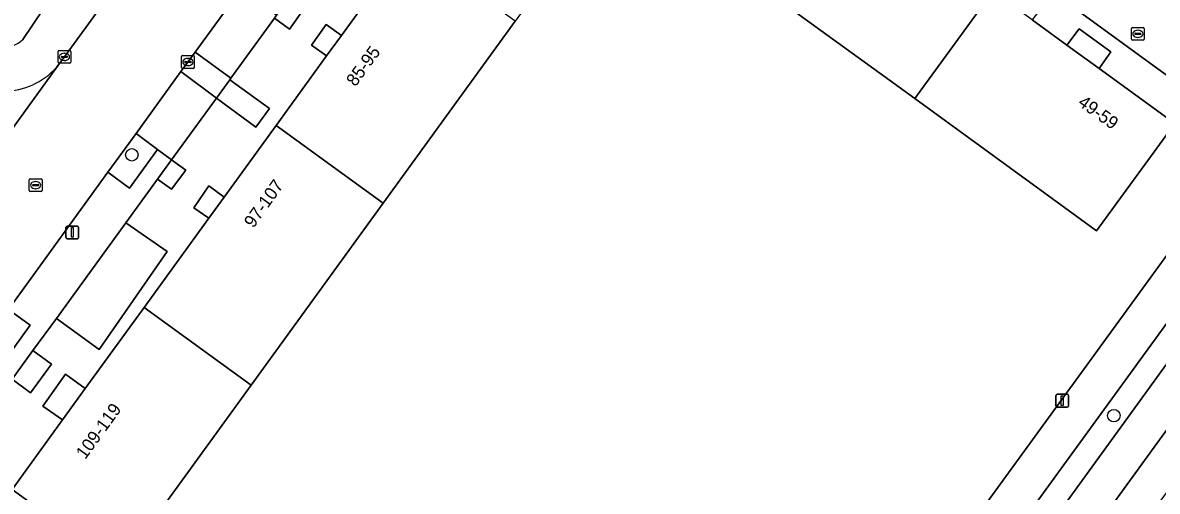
# Model space of a CAD drawing. Extents: x 159674 to 160531, y 382172 to 382904.
# Drawn here: x 160250.3 to 160339.1, y 382520.6 to 382557.3 of the extents above; entities that cross this region are included whole.
import ezdxf

# ---------------------------------------------------------------- set-up
doc = ezdxf.new("R2010")
doc.units = 0
for name, color, linetype in [('IMGEO_Berm_groen', 7, 'Continuous'), ('IMGEO_Boom', 7, 'Continuous'), ('IMGEO_Brandkraan', 7, 'Continuous'), ('IMGEO_Erf', 7, 'Continuous'), ('IMGEO_Fietspad_gesloten', 7, 'Continuous'), ('IMGEO_Groenvoorziening', 7, 'Continuous'), ('IMGEO_Haag', 7, 'Continuous'), ('IMGEO_Kolk', 7, 'Continuous'), ('IMGEO_Lichtmast', 7, 'Continuous'), ('IMGEO_Pand', 7, 'Continuous'), ('IMGEO_Pand_nummerreeks', 7, 'Continuous'), ('IMGEO_Rijbaan_lokaal_gesloten', 7, 'Continuous'), ('IMGEO_Rijbaan_lokaal_open', 7, 'Continuous'), ('IMGEO_Rioolput', 7, 'Continuous'), ('IMGEO_Voetpad_open', 7, 'Continuous')]:
    doc.layers.add(name, color=color, linetype=linetype)

msp = doc.modelspace()

# ---------------------------------------------------------------- linework, layer by layer
at = {"layer": 'IMGEO_Berm_groen'}
for points in [[(160349.002, 382543.246), (160398.827, 382611.342), (160398.73, 382611.41), (160397.047, 382612.59), (160360.539, 382562.246), (160346.84, 382543.397), (160315.294, 382500), (160291.256, 382466.928), (160255.648, 382417.937), (160257.187, 382416.772), (160266.645, 382429.855), (160311.53, 382491.554)], [(160343.873, 382526.012), (160345.353, 382528.03), (160352.635, 382538.399), (160362.897, 382552.659), (160374.83, 382569.169), (160378.396, 382574.452), (160390.705, 382592.122), (160401.931, 382608.929), (160401.131, 382609.485), (160351.662, 382541.731), (160259.615, 382414.865), (160260.653, 382414.245), (160291.094, 382453.563), (160297.701, 382462.662), (160324.815, 382500)]]:
    msp.add_lwpolyline(points, close=True, dxfattribs=at)
at = {"layer": 'IMGEO_Boom'}
for centre in [(160258.813, 382546.917), (160335.675, 382526.506)]:
    msp.add_circle(centre, 0.489, dxfattribs=at)
at = {"layer": 'IMGEO_Brandkraan'}
for p, q in [((160337.057, 382555.962), (160337.057, 382556.814)), ((160337.132, 382556.888), (160337.984, 382556.888)), ((160337.545, 382556.668), (160337.57, 382556.668)), ((160338.058, 382556.814), (160338.058, 382555.962)), ((160337.984, 382555.888), (160337.132, 382555.888)), ((160337.316, 382556.382), (160337.316, 382556.394)), ((160337.754, 382556.345), (160337.356, 382556.345)), ((160337.359, 382556.431), (160337.757, 382556.431)), ((160337.568, 382556.108), (160337.543, 382556.108)), ((160337.8, 382556.394), (160337.8, 382556.382))]:
    msp.add_line(p, q, dxfattribs=at)
for points in [[(160337.057, 382555.962), (160337.057, 382556.814)], [(160337.132, 382556.888), (160337.984, 382556.888)], [(160338.058, 382556.814), (160338.058, 382555.962)], [(160337.984, 382555.888), (160337.132, 382555.888)]]:
    msp.add_lwpolyline(points, dxfattribs=at)
for centre, radius, start, end in [((160337.134, 382556.812), 0.0765, 91.55205, 178.44795), ((160337.134, 382556.812), 0.0765, 91.55205, 178.44795), ((160337.982, 382556.812), 0.0765, 1.55205, 88.44795), ((160337.982, 382556.812), 0.0765, 1.55205, 88.44795), ((160337.134, 382555.964), 0.0765, 181.55205, 268.44795), ((160337.134, 382555.964), 0.0765, 181.55205, 268.44795), ((160337.356, 382556.391), 0.0403, 85.87752, 175.75265), ((160337.353, 382556.381), 0.0366, 178.93798, 274.71019), ((160337.757, 382556.388), 0.043, 264.86636, 352.45326), ((160337.761, 382556.393), 0.0386, 1.73085, 96.63898), ((160337.982, 382555.964), 0.0765, 271.55205, 358.44795), ((160337.982, 382555.964), 0.0765, 271.55205, 358.44795)]:
    msp.add_arc(centre, radius, start, end, dxfattribs=at)
for centre, major_axis, ratio, start_param, end_param in [((160337.544, 382556.388), (-0.387, 0.002), 0.722429, 4.712389, 7.853982), ((160337.569, 382556.388), (-0.39, 0.002), 0.717154, 1.570796, 4.712389)]:
    msp.add_ellipse(centre, major_axis=major_axis, ratio=ratio, start_param=start_param, end_param=end_param, dxfattribs=at)
at = {"layer": 'IMGEO_Erf'}
msp.add_lwpolyline([(160250.273, 382555.941), (160251.85, 382558.275), (160246.728, 382562), (160241.969, 382565.462), (160237.179, 382568.945)], dxfattribs=at)
msp.add_arc((160248.4, 382557.973), 2.764, 274.80019, 312.67073, dxfattribs=at)
at = {"layer": 'IMGEO_Fietspad_gesloten'}
msp.add_lwpolyline([(160351.662, 382541.731), (160401.131, 382609.485), (160403.23, 382612.508), (160404.299, 382614.103), (160401.904, 382615.599), (160398.827, 382611.342), (160349.002, 382543.246), (160311.53, 382491.554), (160266.645, 382429.855), (160257.187, 382416.772), (160254.673, 382413.295), (160254.433, 382412.964), (160257.305, 382411.797), (160259.615, 382414.865)], close=True, dxfattribs=at)
at = {"layer": 'IMGEO_Groenvoorziening'}
for points in [[(160340.442, 382549.369), (160334.331, 382540.968), (160330.288, 382543.909), (160320.097, 382551.321), (160305.863, 382561.673), (160309.033, 382566.031), (160311.974, 382570.074), (160312.894, 382569.405), (160313.791, 382570.579), (160311.658, 382572.109), (160310.584, 382571.385), (160308.218, 382568.127), (160290.343, 382581.143), (160288.198, 382582.705), (160286.206, 382579.962), (160290.265, 382577.019), (160290.699, 382577.618), (160299.084, 382571.539), (160288.827, 382557.394), (160278.496, 382543.145), (160268.164, 382528.897), (160257.833, 382514.648), (160249.448, 382520.727)], [(160293.252, 382483.855), (160291.445, 382481.395), (160295.603, 382478.257), (160311.42, 382500), (160344.923, 382546.056)]]:
    msp.add_lwpolyline(points, dxfattribs=at)
for points in [[(160272.323, 382560.849), (160270.141, 382557.844), (160269.982, 382557.625), (160271.161, 382556.768), (160273.472, 382560.037)], [(160275.215, 382556.263), (160274.018, 382557.131), (160272.871, 382555.506), (160274.059, 382554.669)], [(160332.008, 382555.503), (160334.533, 382553.667), (160335.437, 382554.991), (160332.951, 382556.772)], [(160266.478, 382552.801), (160265.433, 382551.363), (160268.508, 382549.076), (160269.594, 382550.536)], [(160260.836, 382547.345), (160259.145, 382548.59), (160256.944, 382545.554), (160258.645, 382544.321)], [(160261.93, 382546.54), (160260.827, 382545.022), (160261.924, 382544.225), (160263.031, 382545.73)], [(160266.042, 382543.613), (160264.845, 382544.481), (160263.67, 382542.781), (160264.849, 382541.967)], [(160258.34, 382541.598), (160252.908, 382534.119), (160256.263, 382531.683), (160261.573, 382539.364)], [(160249.155, 382534.809), (160247.218, 382532.137), (160248.919, 382530.904), (160250.856, 382533.576)], [(160251.073, 382531.592), (160249.443, 382529.348), (160250.883, 382528.287), (160252.536, 382530.53)], [(160255.17, 382528.62), (160253.623, 382529.742), (160251.861, 382527.246), (160253.392, 382526.166)]]:
    msp.add_lwpolyline(points, close=True, dxfattribs=at)
at = {"layer": 'IMGEO_Haag'}
msp.add_lwpolyline([(160332.008, 382555.503), (160334.533, 382553.667), (160335.437, 382554.991), (160332.951, 382556.772)], close=True, dxfattribs=at)
at = {"layer": 'IMGEO_Kolk'}
for p, q in [((160253.038, 382554.16), (160253.038, 382555.012)), ((160253.113, 382555.086), (160253.965, 382555.086)), ((160253.526, 382554.866), (160253.551, 382554.866)), ((160254.039, 382555.012), (160254.039, 382554.16)), ((160253.965, 382554.086), (160253.113, 382554.086)), ((160253.297, 382554.58), (160253.297, 382554.592)), ((160253.735, 382554.543), (160253.337, 382554.543)), ((160253.34, 382554.629), (160253.738, 382554.629)), ((160253.549, 382554.306), (160253.524, 382554.306)), ((160253.781, 382554.592), (160253.781, 382554.58)), ((160262.704, 382553.762), (160262.704, 382554.614)), ((160262.779, 382554.688), (160263.631, 382554.688)), ((160262.963, 382554.182), (160262.963, 382554.194)), ((160263.401, 382554.145), (160263.003, 382554.145)), ((160263.006, 382554.231), (160263.404, 382554.231)), ((160263.192, 382554.468), (160263.217, 382554.468)), ((160263.447, 382554.194), (160263.447, 382554.182)), ((160263.705, 382554.614), (160263.705, 382553.762)), ((160263.631, 382553.688), (160262.779, 382553.688)), ((160263.215, 382553.908), (160263.19, 382553.908))]:
    msp.add_line(p, q, dxfattribs=at)
for points in [[(160253.038, 382554.16), (160253.038, 382555.012)], [(160253.113, 382555.086), (160253.965, 382555.086)], [(160254.039, 382555.012), (160254.039, 382554.16)], [(160253.965, 382554.086), (160253.113, 382554.086)], [(160262.704, 382553.762), (160262.704, 382554.614)], [(160262.779, 382554.688), (160263.631, 382554.688)], [(160263.705, 382554.614), (160263.705, 382553.762)], [(160263.631, 382553.688), (160262.779, 382553.688)]]:
    msp.add_lwpolyline(points, dxfattribs=at)
for centre, radius, start, end in [((160253.115, 382555.01), 0.0765, 91.55205, 178.44795), ((160253.115, 382555.01), 0.0765, 91.55205, 178.44795), ((160253.963, 382555.01), 0.0765, 1.55205, 88.44795), ((160253.963, 382555.01), 0.0765, 1.55205, 88.44795), ((160253.115, 382554.162), 0.0765, 181.55205, 268.44795), ((160253.115, 382554.162), 0.0765, 181.55205, 268.44795), ((160253.337, 382554.589), 0.0403, 85.87752, 175.75265), ((160253.334, 382554.579), 0.0366, 178.93798, 274.71019), ((160253.738, 382554.586), 0.043, 264.86636, 352.45326), ((160253.742, 382554.591), 0.0386, 1.73085, 96.63898), ((160253.963, 382554.162), 0.0765, 271.55205, 358.44795), ((160253.963, 382554.162), 0.0765, 271.55205, 358.44795), ((160262.781, 382554.612), 0.0765, 91.55205, 178.44795), ((160262.781, 382554.612), 0.0765, 91.55205, 178.44795), ((160263.003, 382554.191), 0.0403, 85.87752, 175.75265), ((160263, 382554.181), 0.0366, 178.93798, 274.71019), ((160263.404, 382554.188), 0.043, 264.86636, 352.45326), ((160263.408, 382554.193), 0.0386, 1.73085, 96.63898), ((160263.629, 382554.612), 0.0765, 1.55205, 88.44795), ((160263.629, 382554.612), 0.0765, 1.55205, 88.44795), ((160262.781, 382553.764), 0.0765, 181.55205, 268.44795), ((160262.781, 382553.764), 0.0765, 181.55205, 268.44795), ((160263.629, 382553.764), 0.0765, 271.55205, 358.44795), ((160263.629, 382553.764), 0.0765, 271.55205, 358.44795)]:
    msp.add_arc(centre, radius, start, end, dxfattribs=at)
for centre, major_axis, ratio, start_param, end_param in [((160253.525, 382554.586), (-0.387, 0.002), 0.722429, 4.712389, 7.853982), ((160253.55, 382554.586), (-0.39, 0.002), 0.717154, 1.570796, 4.712389), ((160263.191, 382554.188), (-0.387, 0.002), 0.722429, 4.712389, 7.853982), ((160263.216, 382554.188), (-0.39, 0.002), 0.717154, 1.570796, 4.712389)]:
    msp.add_ellipse(centre, major_axis=major_axis, ratio=ratio, start_param=start_param, end_param=end_param, dxfattribs=at)
at = {"layer": 'IMGEO_Lichtmast'}
for p, q in [((160253.662, 382540.448), (160253.662, 382541.248)), ((160253.662, 382541.248), (160253.662, 382540.448)), ((160253.762, 382541.348), (160254.552, 382541.348)), ((160254.552, 382541.348), (160253.762, 382541.348)), ((160254.652, 382541.248), (160254.652, 382540.448)), ((160254.652, 382540.448), (160254.652, 382541.248)), ((160254.552, 382540.348), (160253.762, 382540.348)), ((160253.762, 382540.348), (160254.552, 382540.348)), ((160331.146, 382527.278), (160331.146, 382528.078)), ((160331.146, 382528.078), (160331.146, 382527.278)), ((160331.246, 382528.178), (160332.036, 382528.178)), ((160332.036, 382528.178), (160331.246, 382528.178)), ((160332.136, 382528.078), (160332.136, 382527.278)), ((160332.136, 382527.278), (160332.136, 382528.078)), ((160332.036, 382527.178), (160331.246, 382527.178)), ((160331.246, 382527.178), (160332.036, 382527.178))]:
    msp.add_line(p, q, dxfattribs=at)
for points in [[(160254.082, 382541.223), (160254.232, 382541.223), (160254.232, 382540.473), (160254.082, 382540.473), (160254.082, 382541.223)], [(160331.566, 382528.053), (160331.716, 382528.053), (160331.716, 382527.303), (160331.566, 382527.303), (160331.566, 382528.053)]]:
    msp.add_lwpolyline(points, dxfattribs=at)
for centre, start, end in [((160253.762, 382541.248), 90, 180), ((160253.762, 382541.248), 90, 180), ((160254.552, 382541.248), 0, 90), ((160254.552, 382541.248), 360, 90), ((160253.762, 382540.448), 180, 270), ((160253.762, 382540.448), 180, 270), ((160254.552, 382540.448), 270, 0), ((160254.552, 382540.448), 270, 0), ((160331.246, 382528.078), 90, 180), ((160331.246, 382528.078), 90, 180), ((160332.036, 382528.078), 0, 90), ((160332.036, 382528.078), 360, 90), ((160331.246, 382527.278), 180, 270), ((160331.246, 382527.278), 180, 270), ((160332.036, 382527.278), 270, 0), ((160332.036, 382527.278), 270, 0)]:
    msp.add_arc(centre, 0.1, start, end, dxfattribs=at)
at = {"layer": 'IMGEO_Pand'}
for points in [[(160326.208, 382559.722), (160322.918, 382562.114), (160320.177, 382564.108), (160317.558, 382566.013), (160312.894, 382569.405), (160311.974, 382570.074), (160309.033, 382566.031), (160305.863, 382561.673), (160320.097, 382551.321)], [(160288.827, 382557.394), (160280.442, 382563.473), (160275.215, 382556.263), (160274.059, 382554.669), (160270.111, 382549.224), (160278.496, 382543.145)], [(160326.208, 382559.722), (160320.097, 382551.321), (160330.288, 382543.909), (160334.331, 382540.968), (160340.442, 382549.369), (160334.533, 382553.667), (160332.008, 382555.503), (160329.295, 382557.477)], [(160278.496, 382543.145), (160270.111, 382549.224), (160266.042, 382543.613), (160264.849, 382541.967), (160259.779, 382534.976), (160268.164, 382528.897)], [(160268.164, 382528.897), (160259.779, 382534.976), (160255.17, 382528.62), (160253.392, 382526.166), (160249.654, 382521.011), (160249.448, 382520.727), (160257.833, 382514.648)]]:
    msp.add_lwpolyline(points, close=True, dxfattribs=at)
at = {"layer": 'IMGEO_Rijbaan_lokaal_gesloten'}
for points in [[(160315.311, 382639.622), (160304.717, 382625.008), (160302.639, 382622.143), (160290.62, 382605.563), (160279.709, 382590.612), (160279.414, 382590.208), (160269.482, 382576.534), (160263.507, 382568.309), (160253.466, 382554.485), (160253.079, 382553.951), (160242.339, 382539.119), (160232.376, 382525.365), (160226.58, 382517.362), (160218.061, 382505.6), (160216.652, 382503.655), (160216.208, 382503.063), (160216.121, 382502.946), (160214.024, 382500), (160205.773, 382488.409), (160195.682, 382474.429), (160187.988, 382463.77), (160179.328, 382451.773), (160168.227, 382436.541)], [(160249.155, 382534.809), (160256.944, 382545.554), (160259.145, 382548.59), (160262.654, 382553.43), (160263.762, 382554.959), (160267.262, 382559.788), (160279.748, 382577.012), (160283.38, 382582.021), (160283.56, 382582.27), (160285.497, 382584.942), (160285.942, 382585.556), (160295.155, 382598.231), (160297.594, 382601.591), (160301.944, 382607.584), (160305.116, 382611.954), (160310.216, 382618.98), (160313.661, 382623.726), (160314.718, 382625.182), (160318.081, 382629.815)]]:
    msp.add_lwpolyline(points, dxfattribs=at)
at = {"layer": 'IMGEO_Rijbaan_lokaal_open'}
for points in [[(160293.086, 382587.159), (160313.617, 382572.218), (160341.99, 382551.571), (160344.044, 382554.45), (160343.467, 382554.933)], [(160242.339, 382539.119), (160253.079, 382553.951)]]:
    msp.add_lwpolyline(points, dxfattribs=at)
msp.add_arc((160248.746, 382557.494), 5.597, 273.82335, 320.73303, dxfattribs=at)
at = {"layer": 'IMGEO_Rioolput'}
for p, q in [((160250.785, 382544.122), (160250.785, 382544.974)), ((160250.86, 382545.048), (160251.712, 382545.048)), ((160251.044, 382544.542), (160251.044, 382544.554)), ((160251.482, 382544.505), (160251.084, 382544.505)), ((160251.087, 382544.591), (160251.485, 382544.591)), ((160251.296, 382544.268), (160251.271, 382544.268)), ((160251.273, 382544.828), (160251.298, 382544.828)), ((160251.528, 382544.554), (160251.528, 382544.542)), ((160251.786, 382544.974), (160251.786, 382544.122)), ((160251.712, 382544.048), (160250.86, 382544.048))]:
    msp.add_line(p, q, dxfattribs=at)
for points in [[(160250.785, 382544.122), (160250.785, 382544.974)], [(160250.86, 382545.048), (160251.712, 382545.048)], [(160251.786, 382544.974), (160251.786, 382544.122)], [(160251.712, 382544.048), (160250.86, 382544.048)]]:
    msp.add_lwpolyline(points, dxfattribs=at)
for centre, radius, start, end in [((160250.862, 382544.972), 0.0765, 91.55205, 178.44795), ((160250.862, 382544.972), 0.0765, 91.55205, 178.44795), ((160251.084, 382544.551), 0.0403, 85.87752, 175.75265), ((160251.081, 382544.541), 0.0366, 178.93798, 274.71019), ((160251.485, 382544.548), 0.043, 264.86636, 352.45326), ((160251.489, 382544.553), 0.0386, 1.73085, 96.63898), ((160251.71, 382544.972), 0.0765, 1.55205, 88.44795), ((160251.71, 382544.972), 0.0765, 1.55205, 88.44795), ((160250.862, 382544.124), 0.0765, 181.55205, 268.44795), ((160250.862, 382544.124), 0.0765, 181.55205, 268.44795), ((160251.71, 382544.124), 0.0765, 271.55205, 358.44795), ((160251.71, 382544.124), 0.0765, 271.55205, 358.44795)]:
    msp.add_arc(centre, radius, start, end, dxfattribs=at)
for centre, major_axis, ratio, start_param, end_param in [((160251.272, 382544.548), (-0.387, 0.002), 0.722429, 4.712389, 7.853982), ((160251.297, 382544.548), (-0.39, 0.002), 0.717154, 1.570796, 4.712389)]:
    msp.add_ellipse(centre, major_axis=major_axis, ratio=ratio, start_param=start_param, end_param=end_param, dxfattribs=at)
at = {"layer": 'IMGEO_Voetpad_open'}
for points in [[(160401.023, 382623.483), (160399.135, 382620.521), (160346.474, 382548.259), (160344.923, 382546.056), (160311.42, 382500), (160295.603, 382478.257), (160293.955, 382476.039), (160288.608, 382468.68), (160248.967, 382414.122), (160246.396, 382412.259)], [(160254.433, 382412.964), (160254.673, 382413.295), (160257.187, 382416.772), (160255.648, 382417.937), (160291.256, 382466.928), (160315.294, 382500), (160346.84, 382543.397), (160360.539, 382562.246), (160397.047, 382612.59)], [(160311.658, 382572.109), (160313.791, 382570.579), (160312.894, 382569.405), (160317.558, 382566.013), (160318.431, 382567.266), (160321.094, 382565.384), (160320.177, 382564.108), (160322.918, 382562.114), (160323.808, 382563.387), (160330.237, 382558.731), (160329.295, 382557.477), (160332.008, 382555.503), (160332.951, 382556.772), (160335.437, 382554.991), (160334.533, 382553.667), (160340.442, 382549.369), (160344.923, 382546.056), (160346.474, 382548.259), (160341.99, 382551.571), (160313.617, 382572.218)], [(160253.079, 382553.951), (160253.466, 382554.485), (160263.507, 382568.309)], [(160256.431, 382564.573), (160251.85, 382558.275), (160250.273, 382555.941)], [(160249.654, 382521.011), (160253.392, 382526.166), (160251.861, 382527.246), (160253.623, 382529.742), (160255.17, 382528.62), (160259.779, 382534.976), (160264.849, 382541.967), (160263.67, 382542.781), (160264.845, 382544.481), (160266.042, 382543.613), (160270.111, 382549.224), (160274.059, 382554.669), (160272.871, 382555.506), (160274.018, 382557.131), (160275.215, 382556.263), (160280.442, 382563.473)], [(160273.472, 382560.037), (160271.161, 382556.768), (160269.982, 382557.625), (160266.556, 382552.908), (160266.478, 382552.801), (160269.594, 382550.536), (160268.508, 382549.076), (160265.433, 382551.363), (160261.93, 382546.54), (160263.031, 382545.73), (160261.924, 382544.225), (160260.827, 382545.022), (160258.34, 382541.598), (160261.573, 382539.364), (160256.263, 382531.683), (160252.908, 382534.119), (160251.073, 382531.592), (160252.536, 382530.53), (160250.883, 382528.287), (160249.443, 382529.348)]]:
    msp.add_lwpolyline(points, dxfattribs=at)
for points in [[(160269.982, 382557.625), (160270.141, 382557.844), (160267.262, 382559.788), (160263.762, 382554.959), (160266.556, 382552.908)], [(160263.762, 382554.959), (160262.654, 382553.43), (160265.433, 382551.363), (160266.478, 382552.801), (160266.556, 382552.908)], [(160265.433, 382551.363), (160262.654, 382553.43), (160259.145, 382548.59), (160260.836, 382547.345), (160261.93, 382546.54)], [(160258.34, 382541.598), (160260.827, 382545.022), (160261.93, 382546.54), (160260.836, 382547.345), (160258.645, 382544.321), (160256.944, 382545.554), (160249.155, 382534.809), (160250.856, 382533.576), (160248.919, 382530.904), (160247.218, 382532.137), (160246.675, 382531.388), (160249.443, 382529.348), (160251.073, 382531.592), (160252.908, 382534.119)]]:
    msp.add_lwpolyline(points, close=True, dxfattribs=at)
for centre, radius, start, end in [((160248.4, 382557.973), 2.764, 274.80019, 312.67073), ((160248.746, 382557.494), 5.597, 273.82335, 320.73303)]:
    msp.add_arc(centre, radius, start, end, dxfattribs=at)

# ---------------------------------------------------------------- texts
at = {"layer": 'IMGEO_Pand_nummerreeks'}
for s, rotation, p in [('85-95', 54.05284, (160276.32, 382552.201)), ('49-59', 324.05789, (160332.795, 382550.852)), ('97-107', 54.45964, (160268.33, 382541.128)), ('109-119', 54.05284, (160255.168, 382523.029))]:
    msp.add_text(s, height=1, rotation=rotation, dxfattribs=at).set_placement(p)

doc.saveas('drawing.dxf')
